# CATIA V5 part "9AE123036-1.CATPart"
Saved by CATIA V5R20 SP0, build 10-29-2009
Part number: 9AE123036-1
Revision: ANY
Definition: UNKNOWN
Nomenclature: 9AE123036-1
Source: Unknown
Bounding box of the stored display mesh (mm): x -16.35 to 5.15, y -53 to 55, z -10.587 to 10.587
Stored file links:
  C:\Users\Utente\Desktop\IO LAVORO\3D X SITO CF\CUMSA\3D files AE\9AE123036-1.CATPart
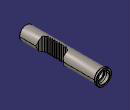
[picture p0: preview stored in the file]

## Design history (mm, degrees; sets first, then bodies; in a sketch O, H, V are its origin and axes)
Body1 "Cortar-Extruir4" (main body)
  Solid1: solid without history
